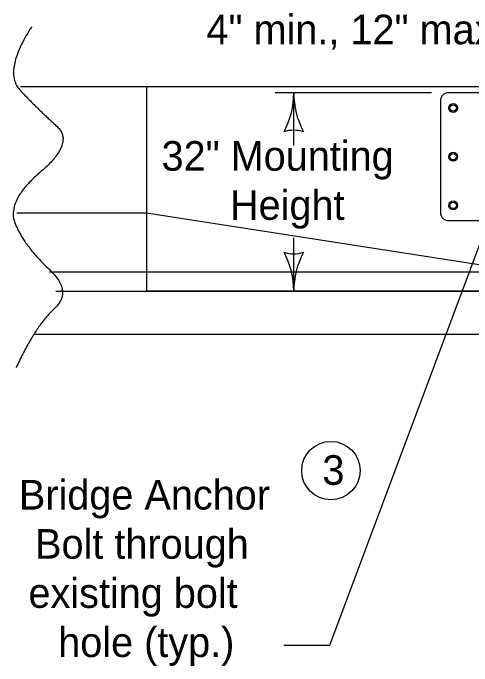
# Model space of a CAD drawing. Extents: x -2137026 to -2131464, y -2138478 to -2136524.
# Drawn here: x -2137009.4 to -2136774, y -2138307 to -2137972.2 of the extents above; entities that cross this region are included whole.
import ezdxf

# ---------------------------------------------------------------- set-up
doc = ezdxf.new("R2010")
doc.units = 0
for name, color, linetype in [('conPaving', 7, 'Continuous'), ('Level 2', 7, 'Continuous'), ('Level 3', 7, 'Continuous'), ('Level 9', 7, 'Continuous')]:
    doc.layers.add(name, color=color, linetype=linetype)

msp = doc.modelspace()

# ---------------------------------------------------------------- linework, layer by layer
at = {"layer": 'conPaving'}
for p, q in [((-2136691.89, -2138013.05), (-2136786.1, -2138013.05)), ((-2136790.2, -2138017.14), (-2136790.2, -2138074.49)), ((-2136786.1, -2138078.58), (-2136691.89, -2138078.58))]:
    msp.add_line(p, q, dxfattribs=at)
for centre, start, end in [((-2136786.1, -2138017.14), 90, 180), ((-2136786.1, -2138074.49), 180, 270)]:
    msp.add_arc(centre, 4.1, start, end, dxfattribs=at)
at = {"layer": 'Level 2'}
for p, q in [((-2136940.96, -2138009.96), (-2137005.68, -2138009.96)), ((-2136940.96, -2138009.96), (-2136940.96, -2138114.82)), ((-2136691.9, -2138009.96), (-2136940.96, -2138009.96)), ((-2136794.68, -2138013.05), (-2136874.97, -2138013.05)), ((-2136865.39, -2138040), (-2136865.39, -2138013.05)), ((-2136846.85, -2138296.37), (-2136759.19, -2138061.56)), ((-2136940.96, -2138074.8), (-2137007.56, -2138074.8)), ((-2136746.34, -2138105.06), (-2136940.96, -2138074.8)), ((-2136865.39, -2138114.82), (-2136865.39, -2138087.37)), ((-2136746.34, -2138105.06), (-2136940.96, -2138105.06)), ((-2136870.46, -2138296.37), (-2136846.85, -2138296.37))]:
    msp.add_line(p, q, dxfattribs=at)
msp.add_circle((-2136846.35, -2138206.8), 15, dxfattribs=at)
for centre, radius, start, end in [((-2136907.89, -2138013.05), 42.5, 331.9275, 360), ((-2136822.89, -2138013.05), 42.5, 180, 208.0725), ((-2136865.39, -2138048.68), 16.42, 72.2666, 107.7334), ((-2136865.39, -2138079.18), 16.42, 252.2666, 287.7333), ((-2136907.89, -2138114.82), 42.5, 360, 28.0725), ((-2136822.89, -2138114.82), 42.5, 151.9275, 180)]:
    msp.add_arc(centre, radius, start, end, dxfattribs=at)
at = {"layer": 'Level 3'}
msp.add_line((-2136691.93, -2138114.82), (-2136940.96, -2138114.82), dxfattribs=at)
at = {"layer": 'Level 9'}
for p, q in [((-2136691.89, -2138013.05), (-2136786.1, -2138013.05)), ((-2136691.89, -2138013.05), (-2136786.1, -2138013.05)), ((-2136790.2, -2138017.14), (-2136790.2, -2138074.49)), ((-2136790.2, -2138017.14), (-2136790.2, -2138074.49)), ((-2136786.1, -2138078.58), (-2136691.89, -2138078.58)), ((-2136786.1, -2138078.58), (-2136691.89, -2138078.58)), ((-2136940.96, -2138105.06), (-2136990.78, -2138105.06)), ((-2136987.54, -2138114.82), (-2134196.38, -2138114.82)), ((-2136998.61, -2138136.77), (-2136691.9, -2138136.77))]:
    msp.add_line(p, q, dxfattribs=at)
for centre, radius in [((-2136783.64, -2138020.85), 2.3), ((-2136783.64, -2138020.85), 1.64), ((-2136783.64, -2138020.85), 1.64), ((-2136783.64, -2138045.83), 2.3), ((-2136783.64, -2138045.83), 1.64), ((-2136783.64, -2138045.83), 1.64), ((-2136783.64, -2138070.8), 2.3), ((-2136783.64, -2138070.8), 1.64), ((-2136783.64, -2138070.8), 1.64)]:
    msp.add_circle(centre, radius, dxfattribs=at)
for centre, start, end in [((-2136786.1, -2138017.14), 90, 180), ((-2136786.1, -2138017.14), 90, 180), ((-2136786.1, -2138074.49), 180, 270), ((-2136786.1, -2138074.49), 180, 270)]:
    msp.add_arc(centre, 4.1, start, end, dxfattribs=at)
msp.add_open_spline([(-2136999.85, -2137979.14), (-2137014.94, -2138002.23), (-2136996.3, -2138021.76), (-2136977.67, -2138038.63), (-2137013.17, -2138068.82), (-2137003.4, -2138091.9), (-2136978.56, -2138114.99), (-2136998.08, -2138132.74), (-2137007.84, -2138154.05)], degree=2, dxfattribs=at)

# ---------------------------------------------------------------- texts
at = {"layer": 'Level 2'}
msp.add_text('3', height=15.2, dxfattribs=at).set_placement((-2136850.73, -2138214.09))
at = {"layer": 'Level 3'}
for s, p in [('4" min., 12" max.', (-2136910.21, -2137988.16)), ('32" Mounting', (-2136933.24, -2138053)), ('Height', (-2136898.14, -2138078.2)), ('Bridge Anchor', (-2137006.42, -2138226.78)), ('Bolt through', (-2136998.11, -2138251.98)), ('existing bolt ', (-2137001.51, -2138277.18)), ('hole (typ.)', (-2136986.25, -2138302.38))]:
    msp.add_text(s, height=15.2, dxfattribs=at).set_placement(p)

doc.saveas('drawing.dxf')
